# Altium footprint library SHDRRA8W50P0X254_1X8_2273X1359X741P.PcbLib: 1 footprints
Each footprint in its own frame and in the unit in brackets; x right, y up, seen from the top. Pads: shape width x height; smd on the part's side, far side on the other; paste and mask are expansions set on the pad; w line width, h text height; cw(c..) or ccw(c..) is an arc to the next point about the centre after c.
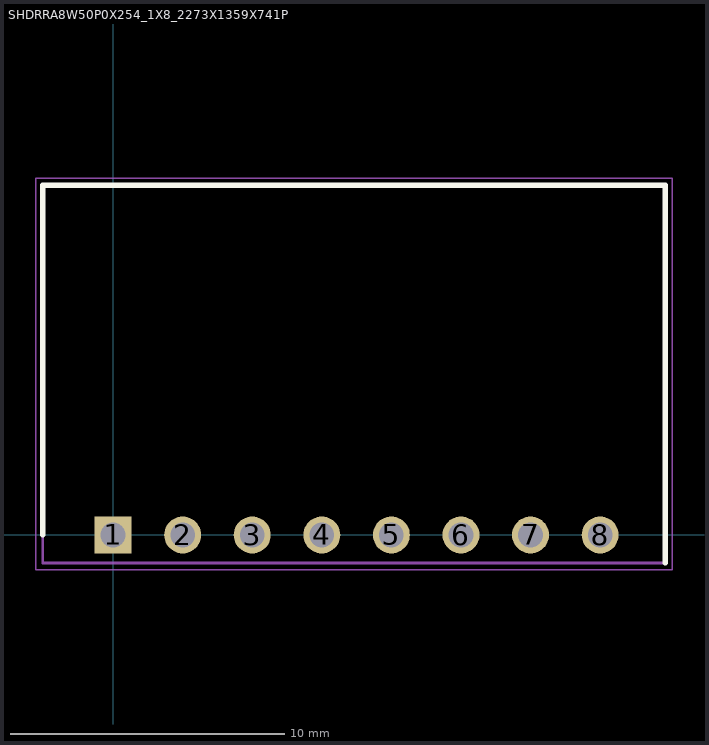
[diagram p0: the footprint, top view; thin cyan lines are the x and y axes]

## SHDRRA8W50P0X254_1X8_2273X1359X741P [mm]
pads (8):
  rect 1.35x1.35 / inner round 1.35 / far side rect 1.35x1.35 hole 0.9: 1(0,0)
  round 1.35 hole 0.9: 2(2.54,0) 3(5.08,0) 4(7.62,0) 5(10.16,0) 6(12.7,0) 7(15.24,0) 8(17.78,0)
Top Overlay:
  lines w0.2: -2.57,0 -2.57,12.77 20.16,12.77 20.16,-1.02
Mechanical 15:
  lines w0.1: -2.57,-1.02 -2.57,12.77 20.16,12.77 20.16,-1.02 -2.57,-1.02
Mechanical 20:
  lines w0.05: -2.82,-1.27 20.41,-1.27 20.41,13.02 -2.82,13.02 -2.82,-1.27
